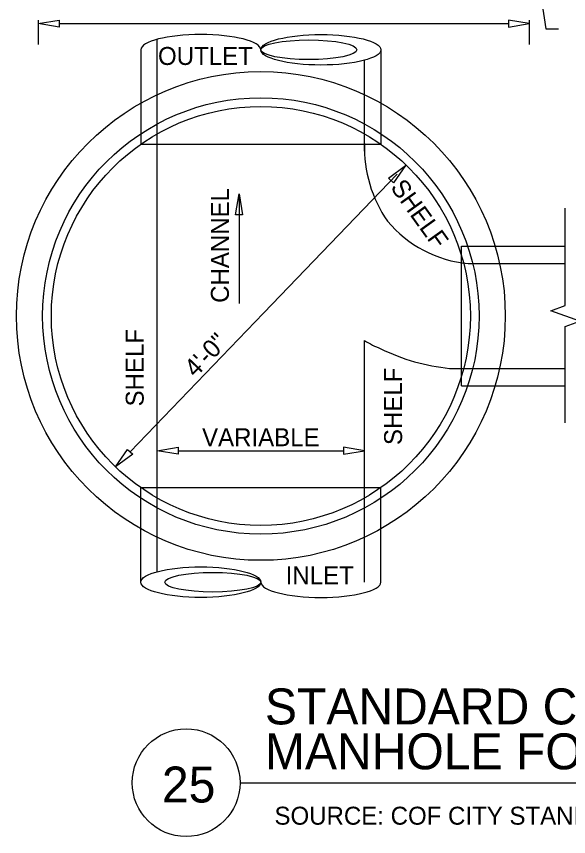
# Model space of a CAD drawing. Extents: x 6712067 to 6713867, y 1867712 to 1869162.
# Drawn here: x 6712759.2 to 6712943.6, y 1868409.5 to 1868683.5 of the extents above; entities that cross this region are included whole.
import ezdxf

# ---------------------------------------------------------------- set-up
doc = ezdxf.new("R2010")
doc.units = 0
for name, color, linetype in [('G-MARK', 7, 'Continuous'), ('G-TEXT', 7, 'Continuous'), ('Misc CnstDet(22)', 7, 'Continuous')]:
    doc.layers.add(name, color=color, linetype=linetype)

msp = doc.modelspace()

# ---------------------------------------------------------------- linework, layer by layer
at = {"layer": 'G-MARK'}
for p, q in [((6712766.51, 1868682.25), (6712766.51, 1868674.06)), ((6712773.51, 1868681.06), (6712923.47, 1868681.06)), ((6712930.47, 1868682.25), (6712930.47, 1868674.06)), ((6712841.76, 1868584.39), (6712886.33, 1868630.75)), ((6712833.58, 1868624.22), (6712833.58, 1868587.57)), ((6712841.76, 1868584.39), (6712797.19, 1868538.02)), ((6712813.21, 1868538.38), (6712868.45, 1868538.38))]:
    msp.add_line(p, q, dxfattribs=at)
for points in [[(6712930.46, 1868716.02), (6712935.98, 1868679.32), (6712940.21, 1868679.32)], [(6712942.48, 1868547.7), (6712942.48, 1868579.92), (6712947.29, 1868581.67), (6712937.68, 1868585.16), (6712942.48, 1868586.92), (6712942.48, 1868619.48)]]:
    msp.add_lwpolyline(points, dxfattribs=at)
at = {"layer": 'G-TEXT'}
for points in [[(6712773.51, 1868682.23), (6712773.51, 1868679.88), (6712766.51, 1868681.06)], [(6712923.47, 1868682.23), (6712923.47, 1868679.88), (6712930.47, 1868681.06)], [(6712885.13, 1868627.86), (6712883.44, 1868629.47), (6712889.13, 1868633.71)], [(6712832.42, 1868617.23), (6712833.58, 1868624.22), (6712834.75, 1868617.23)], [(6712796.35, 1868538.84), (6712798.04, 1868537.22), (6712792.35, 1868532.99)], [(6712813.21, 1868539.55), (6712813.21, 1868537.22), (6712806.22, 1868538.38)], [(6712868.45, 1868539.55), (6712868.45, 1868537.22), (6712875.44, 1868538.38)]]:
    msp.add_lwpolyline(points, close=True, dxfattribs=at)
at = {"layer": 'Misc CnstDet(22)'}
for p, q in [((6712930.47, 1868681.06), (6712930.47, 1868681.06)), ((6712806.22, 1868498.02), (6712806.22, 1868675.82)), ((6712800.76, 1868672.32), (6712800.76, 1868640.75)), ((6712880.91, 1868672.32), (6712880.91, 1868640.75)), ((6712875.44, 1868638.49), (6712875.44, 1868668.82)), ((6712800.76, 1868640.75), (6712880.91, 1868640.75)), ((6712889.32, 1868633.83), (6712889.32, 1868633.83)), ((6712907.87, 1868606.73), (6712942.48, 1868606.73)), ((6712907.87, 1868560.1), (6712907.87, 1868606.73)), ((6712910.06, 1868600.9), (6712942.48, 1868600.9)), ((6712942.48, 1868600.9), (6712942.48, 1868600.9)), ((6712875.44, 1868494.52), (6712875.44, 1868575.18)), ((6712903.86, 1868565.93), (6712942.48, 1868565.93)), ((6712942.48, 1868565.92), (6712942.48, 1868565.92)), ((6712907.87, 1868560.1), (6712942.48, 1868560.1)), ((6712806.22, 1868538.44), (6712806.22, 1868545.38)), ((6712875.44, 1868538.44), (6712875.44, 1868545.38)), ((6712875.44, 1868538.38), (6712875.44, 1868538.38)), ((6712806.22, 1868535.99), (6712806.22, 1868535.99)), ((6712875.44, 1868535.99), (6712875.44, 1868535.99)), ((6712792.35, 1868532.99), (6712792.35, 1868532.99)), ((6712800.76, 1868494.52), (6712800.76, 1868526.08)), ((6712800.76, 1868526.08), (6712880.91, 1868526.08)), ((6712880.91, 1868494.52), (6712880.91, 1868526.08)), ((6712833.89, 1868427.54), (6713137.28, 1868427.54))]:
    msp.add_line(p, q, dxfattribs=at)
for centre, radius in [((6712840.83, 1868583.42), 81.61), ((6712840.83, 1868583.42), 72.87), ((6712840.83, 1868583.42), 69.95), ((6712815.89, 1868427.54), 18)]:
    msp.add_circle(centre, radius, dxfattribs=at)
for centre, radius, start, end in [((6712918.77, 1868639.73), 43.35, 178.3473, 214.6065), ((6712913.86, 1868640.8), 40.08, 219.8617, 264.5574), ((6712894.49, 1868606.94), 37.04, 239.0468, 248.4827), ((6712909.97, 1868630.77), 65.13, 243.4943, 264.6149)]:
    msp.add_arc(centre, radius, start, end, dxfattribs=at)
for centre, major_axis in [((6712820.79, 1868672.32), (-20.04, 0)), ((6712860.87, 1868494.51), (20.04, 0))]:
    msp.add_ellipse(centre, major_axis=major_axis, ratio=0.254545, start_param=3.141593, end_param=6.283185, dxfattribs=at)
for centre, major_axis, ratio in [((6712860.87, 1868672.32), (20.04, 0), 0.254545), ((6712856.86, 1868672.32), (-16.03, 0), 0.204545), ((6712820.79, 1868494.51), (-20.04, 0), 0.254545), ((6712824.8, 1868494.51), (16.03, 0), 0.204545)]:
    msp.add_ellipse(centre, major_axis=major_axis, ratio=ratio, dxfattribs=at)

# ---------------------------------------------------------------- texts
for s, height, p in [('OUTLET', 6, (6712806.49, 1868667.26)), ('VARIABLE', 6, (6712821.2, 1868539.92)), ('INLET', 6, (6712849.11, 1868493.82)), ('STANDARD CAST IN PLACE', 12, (6712842.19, 1868447.01)), ('MANHOLE FOR SEWER', 12, (6712842.19, 1868432.01)), ('25', 12, (6712807.8, 1868420.93)), ('SOURCE: COF CITY STANDARD PLANS, FEBRUARY 2007', 6, (6712845.38, 1868413.52))]:
    msp.add_text(s, height=height, dxfattribs=at).set_placement(p)
for s, rotation, p in [('SHELF', 305.6619, (6712883.88, 1868626.34)), ('CHANNEL', 90, (6712830.16, 1868587.8)), ('SHELF', 90, (6712801.72, 1868553.21)), ('4\'-0"', 46.1233, (6712818.98, 1868562.62)), ('SHELF', 90, (6712887.99, 1868540.31))]:
    msp.add_text(s, height=6, rotation=rotation, dxfattribs=at).set_placement(p)

doc.saveas('drawing.dxf')
